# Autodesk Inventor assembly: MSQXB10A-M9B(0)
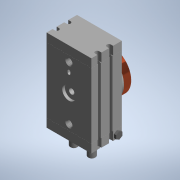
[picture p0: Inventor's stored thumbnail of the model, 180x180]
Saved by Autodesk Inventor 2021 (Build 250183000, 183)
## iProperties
Part Number: MSQXB10A-M9B(0)
Catalog Web Link: www.cadenas.de
Description: MSQX-Low-Speed Rotary Table Rack & Pinion Style
Document SubType Name: Assembly
Designer: partserver
Mass: 168.018 g
Surface Area: 337.625 cm^2
Volume: 168.018 cm^3
Density: 1 g/cm^3
Category: PARTsolutions
PSOL_IDENT_0: {$CADENAS_DATA\23d-libs\smc_jp\actuator\rotary_actuator\msqx\msqx_asmtab.prj},218 {VTYP=3D},{STYP=AS
PSOL_IDENT_1: STAB},{NB=MSQXB10A-M9B(0)},{LINA=MSQXB10A-M9B},{NN=MSQX},{DATE=09.12.2020 02:49:37},{GEOMDATE=09.03.
PSOL_IDENT_2: 2020 10:24:15},{VERSION=},{LINEID=160},{WBVAR=THREAD1,AUTOSW,LEAD,NUMBER,OMSC,THREAD},{WBNUMERIC=}
PSOL_IDENT_3: {NB=MSQXB10A-M9B(0)},{LINA=MSQXB10A-M9B},{KT=DUMMY},{ORDER=MSQXB10A-M9B},{SIZE=10},{THREAD1=},{AUTOS
PSOL_IDENT_4: W=-M9B},{LEAD=},{LEADX= '','(-) 0.5 m' , 'M','(M) 1 m' , 'L','(L) 3 m' , 'Z','(Z) 5 m' },{NUMBER=},{
PSOL_IDENT_5: SWSIGNX= '','(-) 2 pcs' , 'S','(S) 1 pc' },{PORTX= '', '(-) M5' },{OMSC=},{THREAD=0},{NENN=MSQXB10},
PSOL_IDENT_6: {MODEL=MSQXB10A-M9B},{X=},{TIF=1},{AA=55.4},{A=50},{AU=8.6},{AV=20.0},{AW=15.5},{AX=12},{AY=4},{BA=9
PSOL_IDENT_7: .5},{BB=34.5},{BC=27.8},{BD=60},{BE=27},{CA=4.5},{CB=28.5},{D=45h9},{D1=45},{DD=46h9},{DD1=46},{DE=2
PSOL_IDENT_8: 0H9},{DE1=20},{DF=6},{DG=15H9},{DG1=15},{FA=8.0},{FB=4.0},{FC=3.0},{FD=4.5},{H=13},{J=6.8},{JA=11.0}
PSOL_IDENT_9: ,{JB=6.5},{JC=M8x1.25},{JC1=8},{JCP=1.25},{JD=12},{JJ=M5x0.8},{JJ1=5},{JJP=0.80},{JU=M8x1},{JU1=8},{
PSOL_IDENT_10: JUP=1.0},{P=M5x0.8},{P1=5.000},{PP=0.8},{Q=34},{S=92},{SD=9.0},{SE=13},{SF=45},{SU=17.7},{UU=47},{WA=
PSOL_IDENT_11: 15.0},{WB=3H9},{WB1=3},{WC=3.5},{WD=M5x0.8},{WD1=5},{WDP=0.80},{WE=8.0},{WF=32},{XA=27},{XB=3H9},{XB
PSOL_IDENT_12: 1=3},{XC=3.5},{YA=19},{YB=3H9},{YB1=3},{YC=3.5},{F1=6.917},{F2=5},{Y1=8},{Y2=12},{H1=5.000},{H2=5.00
PSOL_IDENT_13: 0},{SWA=61},{SWB=43},{PD=0.3},{EA=47.1},{EB=44.3},{EC=33.5},{ED=14.0},{EE=91.4},{EF=80},{GA=20},{GB=
PSOL_IDENT_14: 15.6},{GC=11},{GD=7.5},{GE=45.2},{K=M8x1},{NA=10.0},{MB=5.5},{NC=12.5},{ND=4},{PPATH=assembly/msqx_a
PSOL_IDENT_15: smsbl.prj}
NB: MSQXB10A-M9B(0)
NN: MSQX
NT: Low-Speed Rotary Table Rack & Pinion Style
NBSYN: $ORDER.($THREAD.)
LINA: MSQXB10A-M9B
CATALOG: SMC (JP
ROWDESC: MSQXB10
SIZE: 10
THREAD1: (-) M5
AUTOSW: M9B Solid state-General-Grommet-Indicator light:Yes-2 wire-In line
LEAD: (-) 0.5 m
NUMBER: (-) 2 pcs
OMSC: (-) Without order
THREAD: on
ARTICLENO: MSQXB10A-M9B(0)
BOMINFO: MSQXB10A-M9B
CREATOR: CADENAS GmbH
Title: MSQXB10A-M9B
Author: Cadenas PARTsolutions
Comments: Low-Speed Rotary Table Rack & Pinion Style
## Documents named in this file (5)
- D:\01 Paralaia\Grupos de Traballo\GT Maquetas\CAD 3D\E_AlimentaciónV1\SMC_JP_MSQXB10AM9B0\MSQXB10A-M9B(0).iam
- D:\01 Paralaia\Grupos de Traballo\GT Maquetas\CAD 3D\E_AlimentaciónV1\SMC_JP_MSQXB10AM9B0\MSQX10(0)_BODY.ipt
- D:\01 Paralaia\Grupos de Traballo\GT Maquetas\CAD 3D\E_AlimentaciónV1\SMC_JP_MSQXB10AM9B0\MSQX10(0)_Table.ipt
- D:\01 Paralaia\Grupos de Traballo\GT Maquetas\CAD 3D\E_AlimentaciónV1\SMC_JP_MSQXB10AM9B0\MSQX_M-5P.ipt
- D:\01 Paralaia\Grupos de Traballo\GT Maquetas\CAD 3D\E_AlimentaciónV1\SMC_JP_MSQXB10AM9B0\D-M9B_MSQX.ipt
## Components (6 placed, 4 different names)
1. MSQX10(0)_BODY:1
2. MSQX10(0)_Table:1 — Insertar:1
3. MSQX_M-5P:1
4. MSQX_M-5P:2
5. D-M9B_MSQX:1
6. D-M9B_MSQX:2
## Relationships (1: Insert 1)
- Insertar:1: MSQX10(0)_Table:1
